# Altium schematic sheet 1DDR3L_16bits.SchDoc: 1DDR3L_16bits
size A3; Date: Not used; ApprovedBy: Not used; CheckedBy: Not used; Author: Not used; CompanyName: STMicroelectronics; DrawnBy: Not used; Engineer: Not used; Organization: Not used; Address1: Not used; Address2: Not used; Address3: Not used; Address4: Not used; DocumentNumber: Not used; Revision: Not used; SheetNumber: 7; SheetTotal: 7
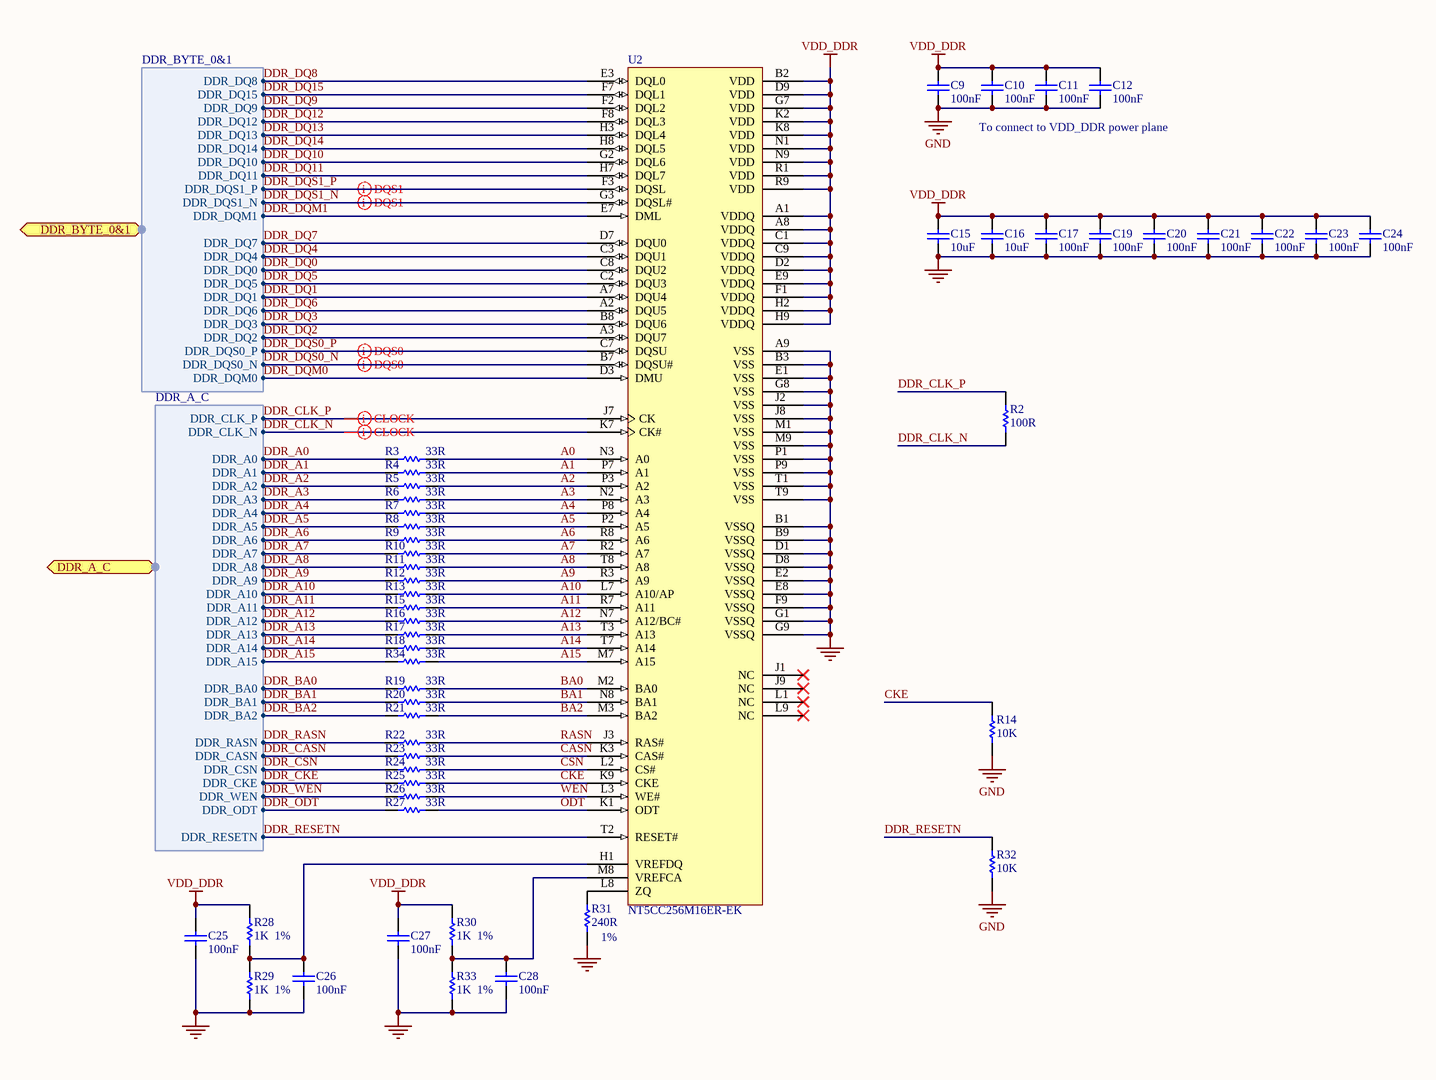
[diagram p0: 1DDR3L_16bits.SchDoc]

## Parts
C9  value 100nF  [C0402]
C10  value 100nF  [C0402]
C11  value 100nF  [C0402]
C12  value 100nF  [C0402]
C15  value 10uF  [C0603]
C16  value 10uF  [C0603]
C17  value 100nF  [C0402]
C19  value 100nF  [C0402]
C20  value 100nF  [C0402]
C21  value 100nF  [C0402]
C22  value 100nF  [C0402]
C23  value 100nF  [C0402]
C24  value 100nF  [C0402]
C25  value 100nF  [C0402]
C26  value 100nF  [C0402]
C27  value 100nF  [C0402]
C28  value 100nF  [C0402]
R2  value 100R  [R0402]
R3  value 33R  [R0402]
R4  value 33R  [R0402]
R5  value 33R  [R0402]
R6  value 33R  [R0402]
R7  value 33R  [R0402]
R8  value 33R  [R0402]
R9  value 33R  [R0402]
R10  value 33R  [R0402]
R11  value 33R  [R0402]
R12  value 33R  [R0402]
R13  value 33R  [R0402]
R14  value 10K  [R0402]
R15  value 33R  [R0402]
R16  value 33R  [R0402]
R17  value 33R  [R0402]
R18  value 33R  [R0402]
R19  value 33R  [R0402]
R20  value 33R  [R0402]
R21  value 33R  [R0402]
R22  value 33R  [R0402]
R23  value 33R  [R0402]
R24  value 33R  [R0402]
R25  value 33R  [R0402]
R26  value 33R  [R0402]
R27  value 33R  [R0402]
R28  value 1K  [R0402]
R29  value 1K  [R0402]
R30  value 1K  [R0402]
R31  value 240R  [R0402]
R32  value 10K  [R0402]
R33  value 1K  [R0402]
R34  value 33R  [R0402]
U2  NT5CC256M16ER-EK  [ICC_VFBGA96_9x13_P080]

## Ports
DDR_A_C (harness DDR_A_C), DDR_BYTE_0&1 (harness DDR_BYTE_0&1)

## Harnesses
DDR_BYTE_0&1: DDR_DQ8, DDR_DQ15, DDR_DQ9, DDR_DQ12, DDR_DQ13, DDR_DQ14, DDR_DQ10, DDR_DQ11, DDR_DQS1_P, DDR_DQS1_N, DDR_DQM1, DDR_DQ7, DDR_DQ4, DDR_DQ0, DDR_DQ5, DDR_DQ1, DDR_DQ6, DDR_DQ3, DDR_DQ2, DDR_DQS0_P, DDR_DQS0_N, DDR_DQM0
DDR_A_C: DDR_A4, DDR_A0, DDR_A2, DDR_A1, DDR_A6, DDR_A3, DDR_A5, DDR_A7, DDR_A8, DDR_A9, DDR_A14, DDR_A10, DDR_A12, DDR_A11, DDR_BA0, DDR_A13, DDR_BA1, DDR_BA2, DDR_RASN, DDR_CASN, DDR_CSN, DDR_CKE, DDR_WEN, DDR_ODT, DDR_CLK_P, DDR_CLK_N, DDR_RESETN, DDR_A15

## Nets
GND: C9.1 C10.1 C11.1 C12.1 C15.1 C16.1 C17.1 C19.1 C20.1 C21.1 C22.2 C23.1 C24.1 C25.1 C26.1 C27.1 C28.1 R14.1 R29.1 R31.1 R32.1 R33.1 U2.A9(VSS) U2.B1(VSSQ) U2.B3(VSS) U2.B9(VSSQ) U2.D1(VSSQ) U2.D8(VSSQ) U2.E1(VSS) U2.E2(VSSQ) U2.E8(VSSQ) U2.F9(VSSQ) U2.G1(VSSQ) U2.G8(VSS) U2.G9(VSSQ) U2.J2(VSS) U2.J8(VSS) U2.M1(VSS) U2.M9(VSS) U2.P1(VSS) U2.P9(VSS) U2.T1(VSS) U2.T9(VSS)
VDD_DDR: C9.2 C10.2 C11.2 C12.2 C15.2 C16.2 C17.2 C19.2 C20.2 C21.2 C22.1 C23.2 C24.2 C25.2 C27.2 R28.2 R30.2 U2.A1(VDDQ) U2.A8(VDDQ) U2.B2(VDD) U2.C1(VDDQ) U2.C9(VDDQ) U2.D2(VDDQ) U2.D9(VDD) U2.E9(VDDQ) U2.F1(VDDQ) U2.G7(VDD) U2.H2(VDDQ) U2.H9(VDDQ) U2.K2(VDD) U2.K8(VDD) U2.N1(VDD) U2.N9(VDD) U2.R1(VDD) U2.R9(VDD)
A0: R3.2 U2.N3(A0)
A1: R4.2 U2.P7(A1)
A2: R5.2 U2.P3(A2)
A3: R6.2 U2.N2(A3)
A4: R7.2 U2.P8(A4)
A5: R8.2 U2.P2(A5)
A6: R9.2 U2.R8(A6)
A7: R10.2 U2.R2(A7)
A8: R11.2 U2.T8(A8)
A9: R12.2 U2.R3(A9)
A10: R13.2 U2.L7(A10/AP)
A11: R15.2 U2.R7(A11)
A12: R16.2 U2.N7(A12/BC#)
A13: R17.2 U2.T3(A13)
A14: R18.2 U2.T7(A14)
A15: R34.2 U2.M7(A15)
BA0: R19.2 U2.M2(BA0)
BA1: R20.2 U2.N8(BA1)
BA2: R21.2 U2.M3(BA2)
CASN: R23.2 U2.K3(CAS#)
CKE: R14.2 R25.2 U2.K9(CKE)
CSN: R24.2 U2.L2(CS#)
DDR_A0: R3.1 ; port DDR_A_C.DDR_A0
DDR_A1: R4.1 ; port DDR_A_C.DDR_A1
DDR_A2: R5.1 ; port DDR_A_C.DDR_A2
DDR_A3: R6.1 ; port DDR_A_C.DDR_A3
DDR_A4: R7.1 ; port DDR_A_C.DDR_A4
DDR_A5: R8.1 ; port DDR_A_C.DDR_A5
DDR_A6: R9.1 ; port DDR_A_C.DDR_A6
DDR_A7: R10.1 ; port DDR_A_C.DDR_A7
DDR_A8: R11.1 ; port DDR_A_C.DDR_A8
DDR_A9: R12.1 ; port DDR_A_C.DDR_A9
DDR_A10: R13.1 ; port DDR_A_C.DDR_A10
DDR_A11: R15.1 ; port DDR_A_C.DDR_A11
DDR_A12: R16.1 ; port DDR_A_C.DDR_A12
DDR_A13: R17.1 ; port DDR_A_C.DDR_A13
DDR_A14: R18.1 ; port DDR_A_C.DDR_A14
DDR_A15: R34.1 ; port DDR_A_C.DDR_A15
DDR_BA0: R19.1 ; port DDR_A_C.DDR_BA0
DDR_BA1: R20.1 ; port DDR_A_C.DDR_BA1
DDR_BA2: R21.1 ; port DDR_A_C.DDR_BA2
DDR_CASN: R23.1 ; port DDR_A_C.DDR_CASN
DDR_CKE: R25.1 ; port DDR_A_C.DDR_CKE
DDR_CLK_N: R2.1 U2.K7(CK#) ; port DDR_A_C.DDR_CLK_N
DDR_CLK_P: R2.2 U2.J7(CK) ; port DDR_A_C.DDR_CLK_P
DDR_CSN: R24.1 ; port DDR_A_C.DDR_CSN
DDR_DQ0: U2.C8(DQU2) ; port DDR_BYTE_0&1.DDR_DQ0
DDR_DQ1: U2.A7(DQU4) ; port DDR_BYTE_0&1.DDR_DQ1
DDR_DQ2: U2.A3(DQU7) ; port DDR_BYTE_0&1.DDR_DQ2
DDR_DQ3: U2.B8(DQU6) ; port DDR_BYTE_0&1.DDR_DQ3
DDR_DQ4: U2.C3(DQU1) ; port DDR_BYTE_0&1.DDR_DQ4
DDR_DQ5: U2.C2(DQU3) ; port DDR_BYTE_0&1.DDR_DQ5
DDR_DQ6: U2.A2(DQU5) ; port DDR_BYTE_0&1.DDR_DQ6
DDR_DQ7: U2.D7(DQU0) ; port DDR_BYTE_0&1.DDR_DQ7
DDR_DQ8: U2.E3(DQL0) ; port DDR_BYTE_0&1.DDR_DQ8
DDR_DQ9: U2.F2(DQL2) ; port DDR_BYTE_0&1.DDR_DQ9
DDR_DQ10: U2.G2(DQL6) ; port DDR_BYTE_0&1.DDR_DQ10
DDR_DQ11: U2.H7(DQL7) ; port DDR_BYTE_0&1.DDR_DQ11
DDR_DQ12: U2.F8(DQL3) ; port DDR_BYTE_0&1.DDR_DQ12
DDR_DQ13: U2.H3(DQL4) ; port DDR_BYTE_0&1.DDR_DQ13
DDR_DQ14: U2.H8(DQL5) ; port DDR_BYTE_0&1.DDR_DQ14
DDR_DQ15: U2.F7(DQL1) ; port DDR_BYTE_0&1.DDR_DQ15
DDR_DQM0: U2.D3(DMU) ; port DDR_BYTE_0&1.DDR_DQM0
DDR_DQM1: U2.E7(DML) ; port DDR_BYTE_0&1.DDR_DQM1
DDR_DQS0_N: U2.B7(DQSU#) ; port DDR_BYTE_0&1.DDR_DQS0_N
DDR_DQS0_P: U2.C7(DQSU) ; port DDR_BYTE_0&1.DDR_DQS0_P
DDR_DQS1_N: U2.G3(DQSL#) ; port DDR_BYTE_0&1.DDR_DQS1_N
DDR_DQS1_P: U2.F3(DQSL) ; port DDR_BYTE_0&1.DDR_DQS1_P
DDR_ODT: R27.1 ; port DDR_A_C.DDR_ODT
DDR_RASN: R22.1 ; port DDR_A_C.DDR_RASN
DDR_RESETN: R32.2 U2.T2(RESET#) ; port DDR_A_C.DDR_RESETN
DDR_WEN: R26.1 ; port DDR_A_C.DDR_WEN
ODT: R27.2 U2.K1(ODT)
RASN: R22.2 U2.J3(RAS#)
WEN: R26.2 U2.L3(WE#)
NetC26_2: C26.2 R28.1 R29.2 U2.H1(VREFDQ)
NetC28_2: C28.2 R30.1 R33.2 U2.M8(VREFCA)
NetR31_2: R31.2 U2.L8(ZQ)

Not connected (* = marked no-connect by the designer): U2 J1(NC)* J9(NC)* L1(NC)* L9(NC)*

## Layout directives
differential pair: DDR_CLK_N, DDR_CLK_P, DDR_DQS0_N, DDR_DQS0_P, DDR_DQS1_N, DDR_DQS1_P

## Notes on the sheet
- To connect to VDD_DDR power plane
- 1%
- (near R31) 1%

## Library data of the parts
C9-C12 C17 C19-C28 = MCD-00006: Capacitor, MLCC, 100nF, 16V, X7R, 10%, 0402, T=0.5mm; Manufacturer_Part_Number: CC0402KRX7R7BB104; Manufacturer: YAGEO; Alternate_Manufacturer_Part_Number: GCM155R71C104KA55D; Alternate_Manufacturer: MURATA; Provided_By: SUBCO; ECCN_US: EAR99; ECCN_EU: NEC
C15 C16 = MCD-00099: Capacitor, MLCC, 10uF, 10V, X5R, 10%, 0603, T=0,8mm; Manufacturer_Part_Number: GRM188R61A106KE69D; Manufacturer: MURATA; Provided_By: SUBCO; ECCN_US: EAR99; ECCN_EU: NEC
R2 = MCD-00119: Resistor,100R,0402,1%,1/16W; Manufacturer_Part_Number: RC0402FR-07100RL; Manufacturer: YAGEO; Provided_By: SUBCO; ECCN_US: EAR99; ECCN_EU: NEC
R3-R13 R15-R27 R34 = MCD-00455: Resistor,33R,0402,1%,1/16W; Manufacturer_Part_Number: RC0402FR-0733RL; Manufacturer: YAGEO; Provided_By: SUBCO; ECCN_US: EAR99; ECCN_EU: NEC
R14 R32 = MCD-00053: Resistor,10K,0402,1%,1/16W; Manufacturer_Part_Number: RC0402FR-0710KL; Manufacturer: YAGEO; Provided_By: SUBCO; ECCN_US: EAR99; ECCN_EU: NEC
R28-R30 R33 = MCD-00061: Resistor,1K,0402,1%,1/16W; Manufacturer_Part_Number: RC0402FR-071KL; Manufacturer: YAGEO; Provided_By: SUBCO; ECCN_US: EAR99; ECCN_EU: NEC
R31 = MCD-00120: Resistor,240R,0402,1%,1/16W; Manufacturer_Part_Number: RC0402FR-07240RL; Manufacturer: YAGEO; Provided_By: SUBCO; ECCN_US: EAR99; ECCN_EU: NEC
U2 = MCD-01811: Memory,DDR3L,4Gb,256Mbx16,933Mhz,1V35,TFBGA; Part_Type: IC; Manufacturer: NANYA; ECCN_US: tbd; Provided_By: SUBCO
